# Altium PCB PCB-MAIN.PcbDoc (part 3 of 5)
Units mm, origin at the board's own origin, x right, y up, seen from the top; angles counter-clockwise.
Board outline 110 x 75 mm, 8 copper layers (F.Cu, In1.Cu, In2.Cu, In3.Cu, In4.Cu, In5.Cu, In6.Cu, B.Cu); 251 components, 185 nets, 1143 pads, 853 vias.
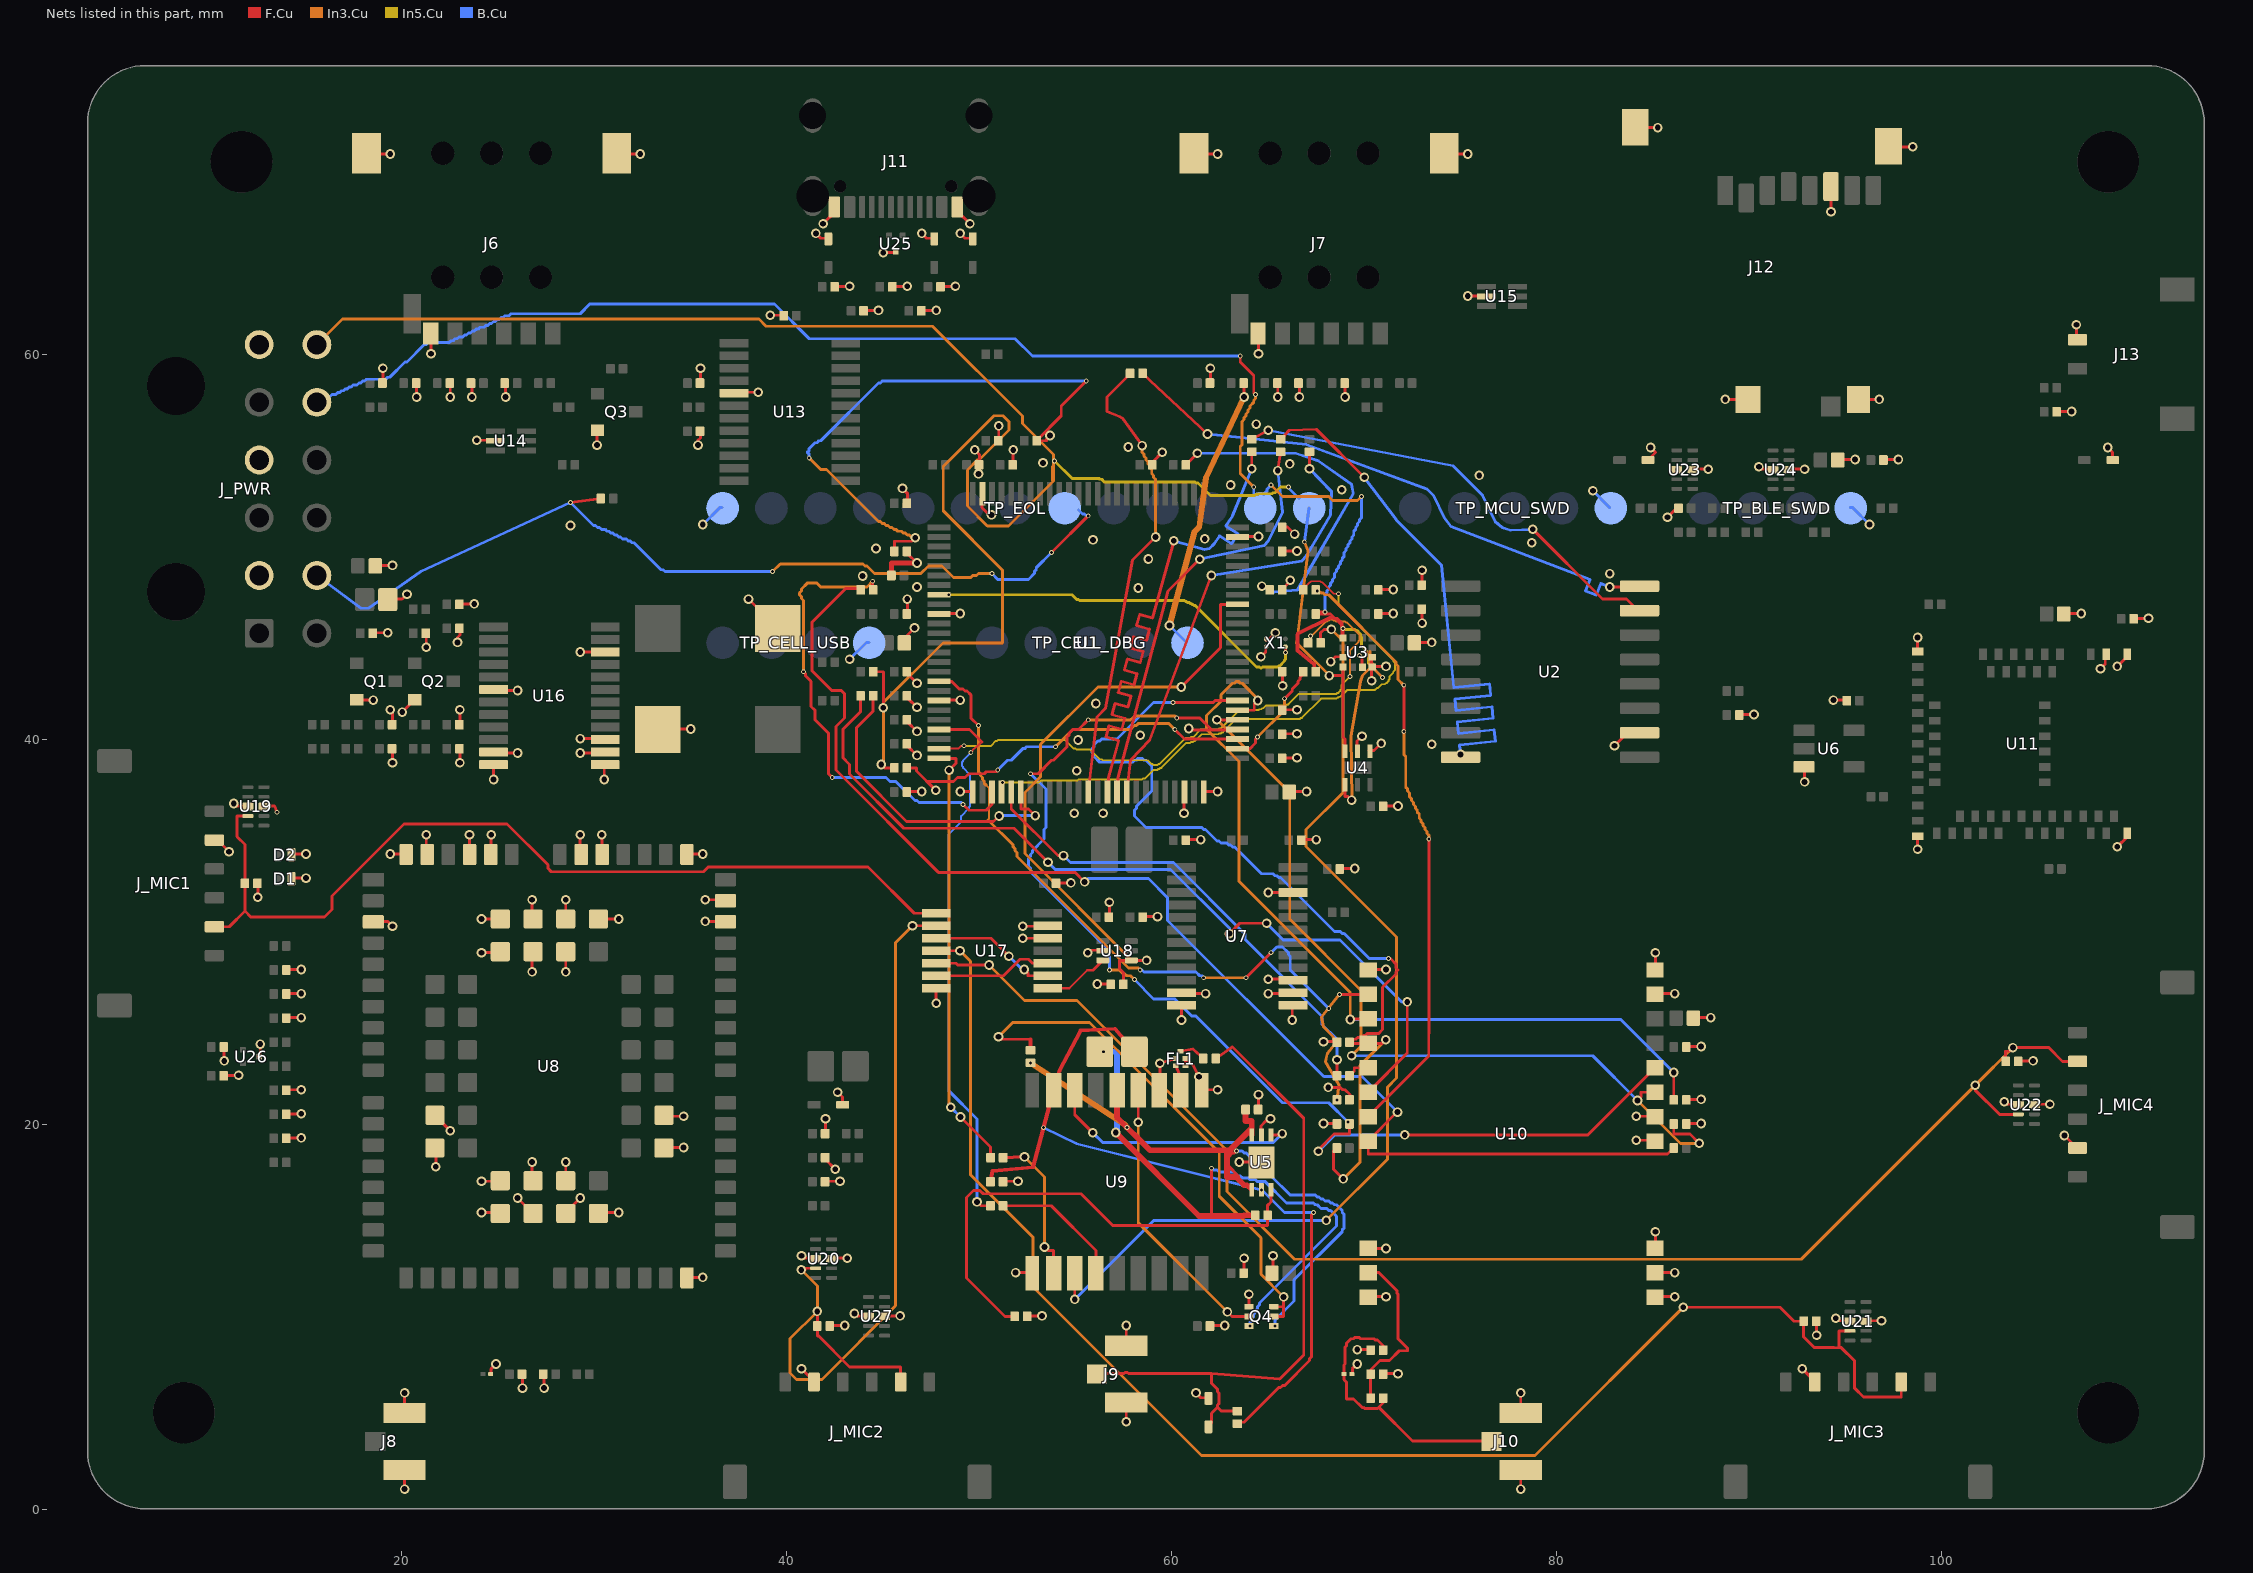
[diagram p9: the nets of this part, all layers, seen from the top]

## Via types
v1: diameter 0.5, hole 0.3, F.Cu to B.Cu, tented both sides, 579 vias
v2: diameter 0.25, hole 0.15, F.Cu to B.Cu, tented both sides, 274 vias

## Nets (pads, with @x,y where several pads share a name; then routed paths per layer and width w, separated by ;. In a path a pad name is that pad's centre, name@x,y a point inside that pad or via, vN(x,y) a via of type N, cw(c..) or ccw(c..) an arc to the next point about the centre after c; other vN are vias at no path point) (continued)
FAULT: J_PWR.8 R103.1 TP_EOL.8 | length 48.2
  F.Cu w0.15: v2(28.785,52.325) R103.1@30.36,52.525 ; v2(53.785,49.725) v2(55.685,51.625)
  In3.Cu w0.15: v2(39.285,48.725) 39.685,49.125 43.985,49.125 44.085,49.025 44.185,49.025 44.585,48.625 46.985,48.625 47.385,49.025 48.085,49.025 48.685,48.425 49.585,48.425 49.685,48.525 49.885,48.525 49.985,48.625 v2(50.685,48.625)
  B.Cu w0.15: J_PWR.8@15.605,48.525 17.885,46.825 18.285,46.825 20.985,48.725 v2(28.785,52.325) 29.985,51.125 30.085,51.125 30.185,51.025 30.285,51.025 30.385,50.925 30.585,50.925 30.685,50.825 30.785,50.825 30.885,50.725 30.985,50.725 31.085,50.625 31.185,50.625 31.285,50.525 31.385,50.525 31.485,50.425 31.685,50.425 31.785,50.325 31.885,50.325 31.985,50.225 32.085,50.225 33.485,48.825 33.585,48.825 33.685,48.725 v2(39.285,48.725) ; v2(50.685,48.625) 50.985,48.325 52.585,48.325 52.885,48.625 52.885,48.725 52.985,48.825 52.985,48.925 v2(53.785,49.725) ; TP_EOL.8@55.185,51.925 55.385,51.725 55.485,51.725 55.585,51.625 v2(55.685,51.625)
GND_DIGITAL: C1.2 C2.2 C3.2 C4.2 C5.2 C6.2 C7.2 C8.2 C9.2 C10.2 C11.2 C12.2 C13.2 C14.2 C15.2 C16.2 C17.2 C18.2 C19.2 C21.2 C22.2 C23.2 C24.2 C25.2 C26.2 C27.2 C28.2 C29.2 C31.2 C32.2 C60.2 C61.2 C62.2 C63.2 C65.2 C66.2 C67.2 C68.2 C69.2 C70.2 C71.2 C72.2 C73.2 C74.2 C75.2 C76.2 C77.2 C78.2 D4.2 D5.2 D6.2 D7.2 D8.2 D9.2 D11.2 FL1.B FL1.D FL1.E J9.SHIELD J10.SHIELD J11.A1 J11.A12 J11.B1 J11.B12 J12.6 J12.SHIELD J13.2 J_PWR.4 Q4.1 R2.2 R3.2 R5.2 R23.2 R60.2 R63.2 R64.2 R65.2 R66.2 R77.2 R93.2 R94.2 R96.2 R97.2 R98.2 TP_BLE_SWD.4 TP_EOL.1 TP_MCU_SWD.5 U1.10 U1.19 U1.26 U1.48 U1.50 U1.74 U1.99 U2.10 U3.3 U3.6 U3.7 U3.8 U4.4 U4.5 U5.5 U5.EP U6.3 U7.11 U7.12 U7.13 U7.14 U7.15 U7.22 U9.1 U9.10 U9.12 U10.1 U10.2 U10.3 U10.4 U10.5 U10.10 U10.11 U10.12 U10.20 U10.22 U11.1 U11.2 U11.15 U11.33 U11.55 U18.2 U23.3 U23.8 U24.3 U24.8 U25.3 X1.1 X1.4 | length 121.2
  F.Cu w0.15: C19.2@19.285,47.3 20.035,47.3 v1(20.285,47.55) ; v1(41.535,66.3) 41.785,66.05 D8.2@42.16,66.05 ; v1(41.91,66.8) 42.535,67.425 J11.B1@42.535,67.675 ; R94.2@42.535,63.55 v1(43.285,63.55) ; R98.2@44.035,62.3 v1(44.785,62.3) ; v1(45.035,65.3) U25.3@45.66,65.3 ; C77.2@45.535,63.55 v1(46.285,63.55) ; v1(46.035,53.05) 46.285,52.8 R96.2@46.285,52.3 ; C6.2@46.16,45.05 46.16,45.3 v1(46.66,45.8) ; C2.2@46.285,37.3 v1(47.035,37.3) ; C10.2@46.285,39.8 46.285,39.675 v1(46.785,39.175) ; C8.2@46.285,41.05 46.285,40.925 v1(46.785,40.425) ; C9.2@46.285,42.3 46.285,42.175 v1(46.785,41.675) ; C11.2@46.285,43.55 46.285,43.425 v1(46.785,42.925) ; C1.2@46.285,46.55 v1(46.285,47.3) ; R5.2@46.285,49.8 46.285,49.675 v1(46.785,49.175) ; R97.2@47.035,62.3 v1(47.785,62.3) ; v1(47.035,66.3) 47.285,66.05 D7.2@47.66,66.05 ; U1.19@47.91,42.05 v1(49.035,42.05) ; U1.10@47.91,46.55 v1(49.035,46.55) ; R93.2@48.035,63.55 v1(48.785,63.55) ; J11.B12@48.91,67.675 48.91,67.425 v1(49.535,66.8) ; v1(49.035,37.3) U1.26@49.66,37.3 ; v1(49.035,66.3) 49.285,66.05 D6.2@49.66,66.05 ; v1(49.785,55.05) 50.035,54.8 C5.2@50.035,54.3 ; U1.99@50.16,52.8 50.16,52.05 50.41,51.8 50.535,51.8 v1(50.66,51.675) ; C17.2@51.035,55.55 v1(51.035,56.3) ; C63.2@51.285,17.05 v1(52.035,17.05) ; C15.2@51.785,54.3 v1(51.785,55.05) ; v1(51.91,12.3) U9.1@52.785,12.3 ; R60.2@52.535,10.05 v1(53.285,10.05) ; v1(55.66,28.925) 55.785,29.05 U18.2@56.41,29.05 ; v1(56.16,27.3) R23.2@56.91,27.3 ; C31.2@56.785,30.8 v1(56.785,31.55) ; v1(57.66,4.55) J9.SHIELD@57.66,5.55 ; J9.SHIELD@57.66,8.55 v1(57.66,9.55) ; C32.2@58.535,30.8 v1(59.285,30.8) ; C18.2@59.035,54.3 59.035,54.425 v1(59.535,54.925) ; U9.12@59.41,21.8 v1(59.41,23.175) FL1.B@60.235,23.425 ; v1(60.535,25.425) U7.12@60.535,26.175 ; U7.11@60.535,26.8 v1(61.785,26.8) ; v1(60.66,36.175) U1.48@60.66,37.3 ; FL1.E@60.735,23.05 FL1.D@60.735,23.425 61.135,23.075 v1(61.435,22.475) ; C27.2@60.785,34.8 v1(61.535,34.8) ; v1(61.285,6.05) 61.535,5.8 D4.2@61.91,5.8 ; U9.10@61.535,21.8 v1(62.41,21.8) ; U1.50@61.66,37.3 v1(62.41,37.3) ; C62.2@62.035,9.55 v1(62.785,9.55) ; U1.74@63.41,50.55 v1(64.535,50.55) ; v1(63.535,18.05) U5.EP@64.66,18.05 ; C60.2@63.785,12.3 v1(63.785,13.05) ; Q4.1@64.035,10.55 v1(64.035,11.175) ; C65.2@64.535,20.8 v1(64.535,21.55) ; U5.5@64.66,19.425 64.66,19.925 64.91,20.175 65.035,20.175 v1(65.16,20.3) ; v1(64.66,44.3) 64.91,44.55 X1.1@64.91,44.8 ; X1.4@64.91,45.175 65.035,45.175 v1(65.41,45.55) ; v1(65.035,26.8) U7.14@66.285,26.8 ; v1(65.035,27.55) U7.15@66.285,27.55 ; v1(65.035,32.05) U7.22@66.285,32.05 ; C61.2@65.285,12.3 v1(65.285,13.175) ; C3.2@65.785,39.05 v1(66.535,39.05) ; C14.2@65.785,40.3 v1(66.535,40.3) ; C16.2@65.785,41.55 v1(66.535,41.55) ; v1(65.785,42.8) R2.2@65.785,43.55 ; R3.2@65.785,47.8 v1(66.185,48.275) ; C12.2@65.785,49.8 v1(66.535,49.8) ; C4.2@65.785,51.05 66.035,51.05 v1(66.41,50.675) ; C13.2@66.16,37.3 v1(67.035,37.3) ; v1(66.285,25.425) U7.13@66.285,26.175 ; C28.2@66.785,34.8 v1(67.535,34.8) ; v1(67.91,20.05) R63.2@68.66,20.05 ; v1(67.91,24.3) C68.2@68.66,24.3 ; v1(68.16,21.925) 68.785,21.925 68.91,21.8 69.035,21.8 69.285,21.55 R65.2@69.285,21.3 ; v1(68.285,44.05) 68.535,44.3 U3.3@68.91,44.3 ; C29.2@68.785,33.3 v1(69.535,33.3) ; D5.2@69.41,7.05 69.41,7.3 v1(69.66,7.55) ; v1(69.66,8.3) C70.2@70.41,8.3 ; U4.5@69.66,39.425 69.66,39.925 v1(69.91,40.175) ; v2(69.785,44.375) 69.91,44.3 U3.6@69.91,43.8 ; U10.22@70.285,11.05 v1(71.16,11.05) ; U10.20@70.285,13.55 v1(71.16,13.55) ; U10.12@70.285,28.05 v1(71.16,28.05) ; U4.4@70.285,39.425 70.535,39.425 v1(70.91,39.8) ; v1(70.41,43.05) U3.8@70.41,44.3 ; U3.7@70.41,43.8 v1(71.16,43.8) ; C23.2@70.785,46.55 v1(71.535,46.55) ; C25.2@70.785,47.8 v1(71.535,47.8) ; C69.2@71.035,7.05 v1(71.785,7.05) ; C26.2@71.035,36.55 v1(71.785,36.55) ; C24.2@72.66,45.05 v1(73.535,45.05) ; v1(73.035,46.05) C21.2@73.035,46.8 ; C22.2@73.035,48.05 v1(73.035,48.8) ; v1(78.16,1.05) J10.SHIELD@78.16,2.05 ; J10.SHIELD@78.16,5.05 v1(78.16,6.05) ; v1(83.035,39.675) 83.66,40.3 U2.10@84.285,40.3 ; v1(84.16,19.175) U10.4@85.16,19.175 ; v1(84.16,20.425) U10.5@85.16,20.425 ; J12.SHIELD@84.16,71.8 v1(85.285,71.8) ; D11.2@84.775,54.525 85.16,54.925 v1(84.91,55.175) ; U10.1@85.16,11.05 v1(86.16,11.05) ; U10.2@85.16,12.3 v1(86.16,12.3) ; U10.3@85.16,13.55 v1(85.16,14.425) ; U10.10@85.16,26.8 v1(86.16,26.8) ; U10.11@85.16,28.05 v1(85.16,28.925) ; v1(85.785,51.55) 86.285,52.05 C76.2@86.41,52.05 ; R64.2@86.785,20.05 v1(87.535,20.05) ; R66.2@86.785,21.3 v1(87.535,21.3) ; C66.2@86.785,24.05 v1(87.535,24.05) ; C67.2@87.16,25.55 v1(88.035,25.55) ; U23.8@87.16,54.05 v1(87.91,54.05) ; v1(88.785,57.675) J12.SHIELD@89.91,57.675 ; R77.2@89.535,41.3 v1(90.285,41.3) ; v1(90.535,54.175) 90.66,54.05 U24.3@91.285,54.05 ; U24.8@92.16,54.05 v1(92.91,54.05) ; v1(92.91,37.8) U6.3@92.91,38.55 ; v1(94.285,67.425) J12.6@94.285,68.675 ; v1(94.41,42.05) C73.2@95.16,42.05 ; C75.2@94.66,54.55 v1(95.535,54.55) ; J12.SHIELD@95.66,57.675 v1(96.785,57.675) ; C74.2@97.035,54.55 v1(97.785,54.55) ; J12.SHIELD@97.285,70.8 v1(98.535,70.8) ; v1(98.785,34.3) U11.33@98.785,34.925 ; U11.15@98.785,44.55 v1(98.785,45.3) ; C78.2@106.035,57.05 v1(106.785,57.05) ; C72.2@106.41,46.55 v1(107.285,46.55) ; J13.2@107.035,60.8 v1(107.035,61.55) ; v1(108.285,43.675) 108.535,43.925 U11.2@108.535,44.425 ; v1(108.66,55.175) 108.91,54.925 D9.2@108.91,54.55 ; v1(109.16,34.425) 109.66,34.925 U11.55@109.66,35.175 ; v1(109.16,43.8) 109.66,44.3 U11.1@109.66,44.425 ; C71.2@110.035,46.3 v1(110.785,46.3)
  F.Cu w0.25: C7.2@45.46,48.525 45.46,49.175 v1(46.785,49.175)
  B.Cu w0.15: v1(35.66,51.175) 36.535,52.05 TP_EOL.1@36.66,52.05 ; v1(81.91,52.925) TP_MCU_SWD.5@82.785,52.05 ; TP_BLE_SWD.4@95.285,52.05 95.41,52.05 v1(96.285,51.175)
  other v1: 54.96,36.175 56.46,36.175 55.085,38.375 73.535,39.75 55.16,39.975 58.385,40.225 56.085,41.875 58.285,47.875 46.785,47.925 43.96,48.5 82.785,48.625 58.814,49.384 44.66,49.925 78.735,50.225 55.935,50.375 61.735,50.425 28.785,51.125 68.86,52.975 63.085,53.225 76.001,53.725 49.985,53.805 66.16,54.325 53.335,54.375 57.76,55.2 64.411,56.392
  other v2: 86.267,54.025
GND_MIC: C20.2 C30.2 J_MIC1.2 J_MIC2.2 J_MIC3.2 J_MIC4.2 J_PWR.6 R19.2 R20.2 R21.2 R22.2 U17.7 U17.12 U17.13 U19.3 U19.8 U20.3 U20.8 U21.3 U21.8 U22.3 U22.8 | length 17.8
  F.Cu w0.15: J_MIC1.2@10.285,34.8 10.41,34.8 v1(11.035,34.175) ; v1(11.285,36.675) 11.41,36.55 U19.3@12.035,36.55 ; v1(12.535,31.8) R19.2@12.535,32.55 ; U19.8@12.91,36.55 13.41,36.55 v2(13.535,36.225) ; C20.2@18.66,49.05 v1(19.535,49.05) ; v1(40.785,7.3) J_MIC2.2@41.41,6.675 ; v1(40.785,13.175) 40.91,13.05 U20.3@41.535,13.05 ; R20.2@42.285,9.55 v1(43.035,9.55) ; U20.8@42.41,13.05 v1(43.16,13.05) ; v1(47.785,26.3) U17.7@47.785,27.05 ; v1(52.285,29.675) U17.12@53.535,29.675 ; v1(52.285,30.3) U17.13@53.535,30.3 ; C30.2@54.035,32.55 v1(54.785,32.55) ; v1(92.785,7.3) J_MIC3.2@93.41,6.675 ; v1(93.535,9.05) R21.2@93.535,9.8 ; v1(94.535,9.925) 94.66,9.8 U21.3@95.285,9.8 ; U21.8@96.16,9.8 v1(96.91,9.8) ; v1(103.285,21.175) 103.41,21.05 U22.3@104.035,21.05 ; R22.2@104.035,23.3 v1(104.785,23.3) ; U22.8@104.91,21.05 v1(105.66,21.05) ; v1(106.41,19.425) J_MIC4.2@107.035,18.8
GND_MODEM: C33.2 C34.2 C35.2 C36.2 C37.2 C38.2 C39.2 C40.2 C41.2 C42.2 C43.2 C44.2 C45.2 C46.2 C47.2 C48.2 C49.2 C50.2 C51.2 C52.2 C53.2 C54.2 C55.2 C56.2 C57.2 C58.2 C59.2 C79.2 C80.2 D1.2 D2.2 D3.2 D10.2 J6.4 J6.SHIELD J7.4 J7.SHIELD J8.SHIELD J_PWR.2 Q1.2 Q2.2 Q3.2 R25.2 R27.2 R29.2 R34.2 R35.2 R45.2 R47.2 TP_CELL_DBG.5 TP_CELL_USB.4 U8.3 U8.31 U8.47 U8.48 U8.50 U8.54 U8.55 U8.58 U8.59 U8.61 U8.62 U8.67 U8.68 U8.69 U8.70 U8.71 U8.72 U8.73 U8.74 U8.79 U8.80 U8.81 U8.82 U8.89 U8.90 U8.91 U8.100 U8.101 U8.102 U13.5 U14.2 U15.2 U16.6 U16.11 U16.12 U16.13 U16.14 U16.15 U16.22 U26.3 U27.3 U27.8 | length 101.3
  F.Cu w0.15: C37.2@10.785,22.55 v1(11.535,22.55) ; v1(10.785,23.3) C38.2@10.785,24.05 ; U26.3@12.66,23.55 v1(12.66,24.175) ; C45.2@14.035,19.3 v1(14.785,19.3) ; C41.2@14.035,20.55 v1(14.785,20.55) ; C39.2@14.035,21.8 v1(14.785,21.8) ; C40.2@14.035,25.55 v1(14.785,25.55) ; C43.2@14.035,26.8 v1(14.785,26.8) ; C47.2@14.035,28.05 v1(14.785,28.05) ; D1.2@14.285,32.8 v1(15.035,32.8) ; D2.2@14.285,34.05 v1(15.035,34.05) ; Q1.2@17.66,42.05 v1(18.535,42.05) ; J6.SHIELD@18.16,70.425 v1(19.41,70.425) ; U8.3@18.535,30.55 19.285,30.55 v1(19.535,30.3) ; R25.2@18.535,45.55 v1(19.285,45.55) ; C50.2@19.035,58.55 v1(19.035,59.3) ; v1(19.41,34.05) U8.62@20.285,34.05 ; v1(19.41,41.55) 19.535,41.425 R27.2@19.535,40.8 ; v1(19.535,38.8) R34.2@19.535,39.55 ; v1(20.035,41.425) Q2.2@20.66,42.05 ; v1(20.16,1.05) J8.SHIELD@20.16,2.05 ; J8.SHIELD@20.16,5.05 v1(20.16,6.05) ; v1(20.785,57.8) C52.2@20.785,58.55 ; U8.61@21.285,34.05 v1(21.285,35.05) ; v1(21.285,44.8) R29.2@21.285,45.55 ; v1(21.535,60.05) J6.4@21.535,61.05 ; v1(21.785,17.8) U8.68@21.785,18.8 ; U8.67@21.785,20.425 v1(22.535,19.675) ; v1(22.535,57.8) C54.2@22.535,58.55 ; v1(22.91,45.05) 22.91,45.3 23.035,45.425 C33.2@23.035,45.8 ; v1(23.035,38.8) C48.2@23.035,39.55 ; C35.2@23.035,40.8 v1(23.035,41.55) ; C34.2@23.035,47.05 v1(23.785,47.05) ; U8.59@23.535,34.05 v1(23.535,35.05) ; v1(23.66,57.8) C55.2@23.66,58.55 ; v1(23.91,55.55) U14.2@24.91,55.55 ; v1(24.16,15.425) U8.69@25.16,15.425 ; v1(24.16,17.05) U8.89@25.16,17.05 ; v1(24.16,28.925) U8.102@25.16,28.925 ; v1(24.16,30.675) U8.82@25.16,30.675 ; D3.2@24.66,7.05 24.66,7.3 v1(24.91,7.55) ; U8.58@24.66,34.05 v1(24.66,35.05) ; v1(24.785,37.925) U16.12@24.785,38.675 ; U16.11@24.785,39.3 v1(26.035,39.3) ; U16.6@24.785,42.55 v1(26.035,42.55) ; v1(25.41,57.8) C56.2@25.41,58.55 ; v1(26.035,16.175) U8.70@26.785,15.425 ; v1(26.285,6.3) C80.2@26.285,7.05 ; U8.90@26.785,17.05 v1(26.785,18.05) ; v1(26.785,27.925) U8.101@26.785,28.925 ; U8.81@26.785,30.675 v1(26.785,31.675) ; v1(27.41,6.3) C79.2@27.41,7.05 ; U8.71@28.535,15.425 v1(29.285,16.175) ; U8.91@28.535,17.05 v1(28.535,18.05) ; v1(28.535,27.925) U8.100@28.535,28.925 ; U8.80@28.535,30.675 v1(28.535,31.675) ; U8.55@29.285,34.05 v1(29.285,35.05) ; v1(29.285,39.3) U16.14@30.535,39.3 ; v1(29.285,40.05) U16.15@30.535,40.05 ; v1(29.285,44.55) U16.22@30.535,44.55 ; v1(30.16,55.3) Q3.2@30.16,56.05 ; U8.72@30.285,15.425 v1(31.285,15.425) ; U8.79@30.285,30.675 v1(31.285,30.675) ; U8.54@30.41,34.05 v1(30.41,35.05) ; v1(30.535,37.925) U16.13@30.535,38.675 ; J6.SHIELD@31.16,70.425 v1(32.41,70.425) ; C36.2@33.285,40.55 v1(35.035,40.55) ; U8.73@33.66,18.8 v1(34.66,18.8) ; U8.74@33.66,20.425 v1(34.66,20.425) ; U8.31@34.785,12.05 v1(35.66,12.05) ; U8.50@34.785,34.05 v1(35.66,34.05) ; v1(35.41,55.3) 35.41,55.55 35.535,55.675 C49.2@35.535,56.05 ; R47.2@35.535,58.55 v1(35.535,59.3) ; v1(35.785,30.55) U8.47@36.785,30.55 ; v1(35.785,31.675) U8.48@36.785,31.675 ; U13.5@37.285,58.05 v1(38.535,58.05) ; v1(38.035,47.3) C44.2@39.535,45.8 ; v1(39.16,62.05) R45.2@39.91,62.05 ; R35.2@42.035,17.05 v1(42.785,17.05) ; C46.2@42.035,18.3 42.035,18.175 v1(42.535,17.675) ; C42.2@42.035,19.55 v1(42.035,20.3) ; v1(42.66,21.675) 42.91,21.425 D10.2@42.91,21.05 ; v1(43.535,10.175) 43.66,10.05 U27.3@44.285,10.05 ; U27.8@45.16,10.05 v1(45.91,10.05) ; J7.SHIELD@61.16,70.425 v1(62.41,70.425) ; C51.2@62.035,58.55 v1(62.035,59.3) ; v1(63.785,57.8) C53.2@63.785,58.55 ; v1(64.535,60.05) J7.4@64.535,61.05 ; v1(65.535,57.8) C57.2@65.535,58.55 ; v1(66.66,57.8) C58.2@66.66,58.55 ; v1(69.035,57.8) C59.2@69.035,58.55 ; J7.SHIELD@74.16,70.425 v1(75.41,70.425) ; v1(75.41,63.05) U15.2@76.41,63.05
  In3.Cu w0.3: v1(59.91,45.925) 61.21,50.8 61.46,51.05 61.81,53.6 v1(63.785,57.8)
  B.Cu w0.15: v1(43.285,44.175) 44.16,45.05 TP_CELL_USB.4@44.285,45.05 ; v1(59.91,45.925) TP_CELL_DBG.5@60.785,45.05
GNSS_ANT_BIAS_RAW: C65.1 Q4.4 R61.1 U5.3 U5.4 U9.14 | length 36.6
  F.Cu w0.15: v2(63.385,18.625) 63.285,18.525 63.185,18.525 62.985,18.325 62.985,17.825 63.485,17.325 63.485,17.225 63.585,17.125 63.585,17.025
  F.Cu w0.25: 63.784,16.85 63.935,16.85 U5.3@64.185,16.6
  F.Cu w0.3: U9.14@57.185,21.775 57.185,20.523 57.185,20.359 58.89,18.654 62.892,18.654 ; 63.784,16.85 63.359,17.275 62.892,17.275 62.892,18.654 ; C65.1@63.86,20.775 63.86,20.173 64.164,20.173 64.185,20.152 64.185,19.801 ; U5.4@64.185,19.45 64.185,19.801 ; 62.892,18.654 63.038,18.654 64.185,19.801
  In3.Cu w0.3: v2(52.685,23.2) 57.585,20 v2(57.702,19.842)
  B.Cu w0.15: v2(63.385,18.625) 63.685,18.625 63.785,18.525 63.885,18.525 65.085,17.325 65.185,17.325 66.185,16.325 67.485,16.325 67.585,16.225 67.685,16.225 67.785,16.125 67.885,16.125 67.985,16.025 68.185,16.025 68.285,15.925 68.385,15.925 68.485,15.825 68.585,15.825 68.885,15.525 68.885,15.425 68.985,15.325 68.985,14.625 68.885,14.525 68.885,14.425 66.385,11.925 66.385,10.825 65.385,9.825 v2(65.385,9.525)
GNSS_ANT_DETECT: U5.6 U9.16 | length 13.5
  F.Cu w0.15: U9.16@54.985,21.775 54.985,20.504 v1(55.924,19.565) ; U5.6@65.185,19.45 65.695,19.45 v1(65.769,19.524)
  B.Cu w0.15: v1(55.924,19.565) 56.435,19.053 65.298,19.053 v1(65.769,19.524)
GNSS_ANT_DIV: R59.2 R60.1 U5.1 | length 26
  F.Cu w0.15: R60.1@51.86,10.025 51.358,10.025 49.364,12.019 49.364,16.206 49.73,16.572 50.053,16.572 50.226,16.4 55.308,16.4 56.96,14.748 65.01,14.748 R59.2@65.01,15.275 65.01,15.802 65.181,15.973 65.185,15.973 U5.1@65.185,16.6
GNSS_ANT_GATE: Q4.5 Q4.6 R61.2 | length 28.3
  F.Cu w0.15: v1(51.025,24.556) 51.156,24.425 51.207,24.425 52.685,24.425 ; Q4.5@65.323,10.025 65.839,10.025 65.839,10.525 ; v1(65.839,11.039) 65.839,10.525 ; 65.839,10.525 Q4.6@65.323,10.525 65.839,10.525
  F.Cu w0.2: R61.2@52.685,23.85 52.685,24.425
  In3.Cu w0.15: v1(51.025,24.556) 51.761,25.292 55.75,25.292 62.497,18.546 62.497,16.271 64.659,14.108 64.659,12.219 v1(65.839,11.039)
GNSS_ANT_OFF_N: Q4.2 U9.13 | length 14.7
  F.Cu w0.15: v1(58.285,20.113) U9.13@58.285,21.775 ; v1(62.919,10.259) 63.153,10.025 Q4.2@64.047,10.025
  In3.Cu w0.15: v1(58.285,20.113) 58.285,14.893 v1(62.919,10.259)
GNSS_ANT_SHORT_N: C63.1 L2.1 R62.2 U5.2 U9.17 | length 41.3
  F.Cu w0.15: L2.1@63.585,4.525 63.785,4.525 65.585,6.325 65.685,6.325 65.785,6.425 65.885,6.425 67.185,7.725 67.185,7.825 67.285,7.925 67.285,15.325 v2(67.385,15.425)
  F.Cu w0.2: C63.1@50.61,17.025 50.71,17.575 52.81,17.775 U9.17@53.885,21.775 54.185,22.775 55.285,24.875 57.085,24.975 R62.2@58.085,23.775
  B.Cu w0.15: v2(53.363,19.831) 55.085,19 v2(64.685,16.6) ; v2@64.685,16.625 65.885,15.425 v2(67.385,15.425)
GNSS_ANT_SWITCHED: Q4.3 R59.1 R62.1 | length 31.6
  F.Cu w0.15: 62.085,15.225 v2(62.085,17.725)
  F.Cu w0.3: v1(57.113,19.58) 61.447,15.246 63.754,15.246 63.783,15.275 R59.1@64.36,15.275
  B.Cu w0.15: v2(62.085,17.725) 62.185,17.625 62.385,17.625 62.485,17.525 63.285,17.525 63.485,17.325 63.585,17.325 63.685,17.225 63.985,17.225 64.085,17.125 64.385,17.125 64.485,17.025 64.885,17.025 65.985,15.925 67.385,15.925 67.485,15.825 67.585,15.825 67.785,15.625 68.085,15.625 68.185,15.525 68.285,15.525 68.585,15.225 68.585,14.725 64.585,10.725 64.585,10.625 64.485,10.525 64.485,10.425 64.385,10.325 64.385,10.225 64.285,10.125 64.285,10.025 64.185,9.925 64.185,9.825 64.085,9.725 v2(64.085,9.525)
  B.Cu w0.3: v2(56.485,23.775) 57.185,23.775 57.185,19.652 v1(57.113,19.58)
GNSS_PPS_U1: R58.2 U1.22 | length 28.8
  F.Cu w0.1: v2(49.585,39.325) 49.685,39.425 49.685,39.475 50.17,39.875
  F.Cu w0.15: U1.22@47.935,40.525 49.52,40.525 50.17,39.875 ; v1(49.907,15.974) 49.909,15.974 50.108,15.775 R58.2@50.61,15.775
  B.Cu w0.1: 48.485,35.125 49.085,35.725 49.085,36.025 49.485,36.425 49.485,36.475 49.535,36.525 49.535,38.175 49.185,38.525 49.185,38.575 49.135,38.625 49.135,38.825 49.185,38.875 49.185,38.925 v2(49.585,39.325)
  B.Cu w0.15: 48.438,35.078 48.438,21.751 49.907,20.282 v1(49.907,15.974)
GNSS_PPS_U9: R58.1 U9.4 | length 7
  F.Cu w0.15: R58.1@51.26,15.775 51.762,15.775 53.762,15.775 56.085,13.452 U9.4@56.085,12.275
GNSS_RF_ANT_BIASED: C64.1 D4.1 J9.1 L2.2 | length 34.1
  F.Cu w0.151: J9.1@56.16,7.05 57.535,7.05 57.597,7.113 57.722,7.113 57.785,7.05 62.097,7.05 ; D4.1@61.91,4.3 62.097,4.488 62.097,4.988 62.41,5.3 ; C64.1@62.31,23.425 63.185,24.025 66.885,20.325 66.885,8.025 65.635,6.775 62.097,7.05 ; L2.2@63.41,5.113 62.597,5.113 62.41,5.3 ; 62.097,7.05 62.097,6.55 62.41,6.238 62.41,6.112 62.472,6.05 62.472,5.487 62.41,5.425 62.41,5.3
GNSS_RF_DC_BLOCK: C64.2 FL1.C | length 1.4
  F.Cu w0.151: FL1.C@60.485,23.8 61.135,23.925 C64.2@61.66,23.425
GNSS_RF_FILTERED: FL1.A U9.11 | length 1.3
  F.Cu w0.151: FL1.A@60.235,23.05 60.485,22.475 U9.11@60.485,21.775
GNSS_RX_U1: R56.2 U1.25 | length 22.7
  F.Cu w0.15: U1.25@47.935,39.025 48.812,39.025 48.812,38.768 v1@48.458,38.414 ; v1(49.046,20.389) 50.61,18.825 R56.2@50.61,18.275
  In3.Cu w0.15: v1(48.456,38.414) 48.456,20.978 v1(48.542,20.893)
  B.Cu w0.15: v1(48.542,20.893) v1(49.046,20.389)
GNSS_RX_U9: R56.1 U9.2 | length 8
  F.Cu w0.15: R56.1@51.26,18.275 51.762,18.275 51.798,18.311 v1(52.374,18.311) ; v1(53.413,13.629) 53.59,13.452 53.885,13.452 U9.2@53.885,12.275
  In3.Cu w0.15: v1(52.374,18.311) 53.413,17.272 v1(53.413,13.629)
GNSS_TX_U1: R57.1 U1.24 | length 29.6
  F.Cu w0.1: U1.24@48.385,39.525 48.935,39.525 49.085,39.675 v2(49.235,39.675) ; R57.1@67.135,45.125 67.185,45.175 67.185,45.225 67.235,45.275 v2(67.235,45.375)
  In3.Cu w0.1: v2(67.235,45.375) 67.285,45.375 68.035,46.125 68.085,46.125 68.135,46.175 68.185,46.175 68.235,46.225 68.385,46.225 68.435,46.175 68.535,46.175 68.585,46.125 69.035,46.125 69.085,46.075 69.135,46.075 69.785,45.425 69.785,45.175 69.735,45.125 69.735,45.075 69.285,44.625 v2(69.285,43.275)
  In5.Cu w0.1: v2(49.235,39.675) 50.635,39.675 50.885,39.925 50.935,39.925 50.985,39.975 54.485,39.975 54.935,39.525 55.035,39.525 55.085,39.475 55.785,39.475 56.285,38.975 56.385,38.975 56.435,38.925 58.785,38.925 58.985,38.725 59.035,38.725 59.085,38.675 59.285,38.675 59.335,38.725 59.385,38.725 60.735,40.075 60.985,40.075 61.035,40.125 61.135,40.125 61.535,40.525 62.435,40.525 62.485,40.575 62.585,40.575 63.535,41.525 64.535,41.525 64.585,41.575 64.685,41.575 64.735,41.625 64.785,41.625 64.935,41.775 65.985,41.775 66.035,41.825 66.085,41.825 66.635,42.375 68.585,42.375 68.635,42.425 68.685,42.425 68.785,42.525 68.785,42.575 68.835,42.625 68.835,42.825 v2(69.285,43.275)
GNSS_TX_U9: R57.2 U9.3 | length 52.5
  F.Cu w0.15: v1(54.985,10.908) U9.3@54.985,12.275 ; R57.2@67.76,45.025 67.76,45.552 67.932,45.724 v1(68.323,45.724)
  In3.Cu w0.15: v1(68.049,15.013) 71.229,18.193 71.229,21.935 71.703,22.408 71.703,29.745 67.005,34.443 67.005,35.327 68.918,37.24 68.918,45.129 v1(68.323,45.724)
  B.Cu w0.15: v1(54.985,10.908) 59.09,15.013 v1(68.049,15.013)
HW_REV0: R3.1 R4.2 | length 18
  F.Cu w0.15: R4.2@60.76,54.275 v1(61.36,54.875) ; v1(64.71,47.975) R3.1@65.11,47.775
  B.Cu w0.15: v1(61.36,54.875) 66.46,54.875 67.66,54.475 69.36,53.275 69.46,52.775 66.56,47.775 65.36,47.675 v1(64.71,47.975)
HW_REV1: R5.1 R6.2 | length 30.1
  F.Cu w0.15: R5.1@45.61,49.775 45.61,50.302 46.509,50.302 v1(46.698,50.491) ; R6.2@53.01,55.525 53.512,55.525 53.512,55.612 v1(53.701,55.801) ; R6.2@53.085,55.625 54.285,56.825 54.285,57.325 v2(55.585,58.625)
  In3.Cu w0.15: v2(41.185,54.625) 41.785,54.025 42.085,54.025 44.785,51.325 44.885,51.325 44.985,51.225 45.085,51.225 45.185,51.125 45.285,51.125 45.385,51.025 45.485,51.025 45.585,50.925 45.685,50.925 45.785,50.825 45.985,50.825 46.085,50.725 46.185,50.725 46.285,50.625 46.385,50.625 46.485,50.525 v1@46.585,50.525
  B.Cu w0.15: v2(41.185,54.625) 41.185,54.825 41.085,54.925 41.185,55.025 41.185,55.125 41.485,55.425 41.585,55.425 41.685,55.525 41.785,55.525 44.785,58.525 44.885,58.525 44.985,58.625 v2(55.585,58.625)
I2C2_SCL_BUS: J_PWR.11 R13.2 R15.2 TP_EOL.12 U3.1 U4.1 | length 93.9
  F.Cu w0.15: v2(63.585,59.925) 63.585,59.625 64.285,58.925 64.285,58.025 v2(64.385,57.925) ; R13.2@67.51,46.525 68.012,46.525 68.267,46.525 68.922,45.87 U3.1@68.922,45.275 ; R13.2@67.585,46.525 67.685,46.625 v2(67.985,46.625) ; U4.1@69.035,37.66 69.035,37.033 69.192,37.033 v1(69.37,36.855)
  F.Cu w0.2: R15.2@67.51,43.525 67.41,43.925 66.56,44.625 66.56,45.425 66.61,45.525 68.26,46.325 68.61,46.275 68.86,46.025 U3.1@68.922,45.275
  In3.Cu w0.15: v2(64.285,53.125) 63.585,53.825 63.585,55.225 63.685,55.325 63.685,56.525 63.785,56.625 63.785,56.725 63.885,56.825 63.885,56.925 63.985,57.025 63.985,57.125 64.085,57.225 64.085,57.325 64.285,57.525 64.285,57.625 64.385,57.725 v2(64.385,57.925) ; v2(65.185,53.225) 65.785,52.625 68.185,52.625 68.385,52.425 69.685,52.425 v2(69.885,52.625) ; v2(68.922,45.77) v2@68.935,45.775 ; v1(69.37,36.855) 69.385,36.875 69.335,40.175 69.835,43.025 69.935,43.325 70.335,43.725 70.335,44.575 70.335,44.075 70.485,43.925 70.485,43.725 v2(70.985,43.225)
  In5.Cu w0.15: v2@69.035,45.725 69.535,45.725 69.585,45.675 69.635,45.675 69.835,45.475 69.835,45.375 69.885,45.325 69.885,44.875 70.185,44.575 70.185,44.475 70.235,44.425 70.235,43.975 v2(70.985,43.225)
  B.Cu w0.15: J_PWR.11@16.185,57.825 16.285,57.825 16.385,57.925 16.585,57.925 16.685,58.025 16.785,58.025 16.885,58.125 16.985,58.125 17.085,58.225 17.185,58.225 17.285,58.325 17.385,58.325 17.485,58.425 17.685,58.425 17.785,58.525 17.885,58.525 17.985,58.625 18.085,58.625 18.185,58.725 19.185,58.725 19.285,58.825 19.385,58.825 20.185,59.625 20.285,59.625 21.185,60.525 21.285,60.525 21.385,60.625 22.485,60.625 22.585,60.725 22.685,60.725 22.785,60.825 22.885,60.825 22.985,60.925 23.185,60.925 23.285,61.025 23.385,61.025 23.485,61.125 23.585,61.125 23.685,61.225 23.785,61.225 23.885,61.325 23.985,61.325 24.085,61.425 24.285,61.425 24.385,61.525 24.485,61.525 24.585,61.625 24.685,61.625 24.785,61.725 24.885,61.725 24.985,61.825 25.085,61.825 25.185,61.925 25.285,61.925 25.385,62.025 25.585,62.025 25.685,62.125 29.285,62.125 29.785,62.625 39.385,62.625 41.185,60.825 51.885,60.825 52.785,59.925 v2(63.585,59.925) ; TP_EOL.12@64.285,52.725 v2(64.285,53.125) ; TP_EOL.12@64.785,52.725 64.985,52.925 64.985,53.025 v2(65.185,53.225) ; v2(67.985,46.625) 67.985,47.525 68.085,47.625 68.085,47.725 68.185,47.825 68.185,47.925 68.285,48.025 68.285,48.125 68.385,48.225 68.385,48.325 68.485,48.425 68.485,48.625 68.585,48.725 68.585,48.825 68.685,48.925 68.685,49.025 68.785,49.125 68.785,49.225 68.885,49.325 68.885,49.425 68.985,49.525 68.985,49.725 69.085,49.825 69.085,49.925 69.185,50.025 69.185,50.125 69.285,50.225 69.285,50.325 69.385,50.425 69.385,50.525 69.485,50.625 69.485,50.825 69.585,50.925 69.585,51.025 69.685,51.125 69.685,51.225 69.785,51.325 69.785,51.425 69.885,51.525 v2(69.885,52.625)
I2C2_SCL_U1: R15.1 U1.52 | length 5.2
  F.Cu w0.15: U1.52@63.885,39.525 64.085,39.525 64.385,39.825 64.385,40.025 v2(64.485,40.125) ; v2(65.885,42.125) 66.285,42.525 66.285,42.625 66.585,42.925 66.585,43.025 66.685,43.125 66.685,43.225 66.785,43.325 R15.1@66.785,43.425
  In3.Cu w0.15: v2(64.485,40.125) 65.885,41.525 v2(65.885,42.125)
I2C2_SDA_BUS: J_PWR.12 R14.2 R16.2 TP_EOL.13 U3.4 U4.6 | length 113.1
  F.Cu w0.15: R14.2@44.51,43.525 45.012,43.525 45.037,43.5 v1(45.037,41.658) ; v1(44.928,38.705) 45.108,38.525 R16.2@45.61,38.525 ; v1(68.215,43.323) 68.922,43.323 ; U3.4@68.922,43.775 68.922,43.323 ; U4.6@69.035,39.39 69.035,40.017 68.922,40.129 68.922,43.323
  In3.Cu w0.15: J_PWR.12@15.605,60.525 16.929,61.849 38.575,61.849 38.946,61.478 47.597,61.478 52.265,56.81 52.265,56.429 53.876,54.818 53.876,53.433 51.54,51.097 50.443,51.097 49.406,52.134 49.406,54.008 49.921,54.523 50.003,54.523 51.562,56.082 51.562,56.518 51.253,56.827 50.788,56.827 48.153,54.192 48.153,51.885 51.238,48.801 51.238,45.021 48.136,45.021 45.037,41.922 v1(45.037,41.658) 45.037,38.814 v1(44.928,38.705) ; 53.835,53.475 53.835,54.175 53.885,54.225 53.885,54.425 v2(53.935,54.475) ; v2(66.915,50.275) 67.115,49.775 66.518,45.021 v1(68.215,43.323)
  In5.Cu w0.15: v2(53.935,54.475) 54.835,53.575 56.235,53.575 56.285,53.525 56.385,53.525 56.535,53.375 61.235,53.375 61.285,53.325 61.385,53.325 62.035,52.675 64.335,52.675 64.385,52.725 64.485,52.725 64.535,52.775 65.235,52.775 65.285,52.825 65.385,52.825 65.685,53.125 v2(66.085,53.125)
  B.Cu w0.15: v2(66.085,53.125) 66.085,53.075 TP_EOL.13@66.635,52.525 ; v2(66.915,50.275) TP_EOL.13@67.165,52.025
I2C2_SDA_U1: R16.1 U1.53 | length 19.4
  F.Cu w0.15: R16.1@46.26,38.525 46.762,38.525 46.762,38.361 v1(47.762,37.361) ; 47.285,37.825 48.685,37.825 48.885,38.025 49.285,38.025 49.485,38.225 50.285,38.225 50.385,38.325 50.885,38.325 v2(50.985,38.425) ; v2(60.185,40.525) 60.685,40.025 U1.53@62.985,40.025
  In3.Cu w0.15: v2(53.985,39.625) 54.885,40.525 57.885,40.525 58.085,40.725 58.185,40.725 58.285,40.825 59.885,40.825 v2(60.185,40.525)
  B.Cu w0.15: v2(50.985,38.425) 51.485,38.925 51.685,38.925 52.285,39.525 52.385,39.525 52.485,39.625 v2(53.985,39.625)
LORA_BUSY: R66.1 U1.56 U10.14 | length 44.6
  F.Cu w0.15: U1.56@63.435,41.525 64.312,41.525 64.312,41.844 v1(64.494,42.027) ; v1(69.304,25.453) 69.335,25.485 U10.14@70.235,25.485 ; R66.1@86.11,21.275 v1(86.11,22.699)
  In3.Cu w0.15: 62.585,42.025 62.585,42.325 63.185,42.925 63.285,42.925 63.385,43.025 63.485,43.025 63.585,42.925 63.685,42.925 v1@64.485,42.125 ; 62.62,42.027 61.838,41.245 61.838,40.534 63.514,38.859 63.514,32.639 69.304,26.849 v1(69.304,25.453)
  B.Cu w0.15: v1(69.304,25.453) 83.356,25.453 v1(86.11,22.699)
LORA_DIO1: R65.1 U1.17 U10.13 | length 39.9
  F.Cu w0.15: U1.17@48.385,43.025 48.585,43.025 48.985,42.625 49.185,42.625 49.285,42.525 49.385,42.525 49.585,42.325 49.585,41.125 v2(49.985,40.725) ; v2(63.885,27.625) v2(65.185,28.925) ; v2(68.735,26.755) U10.13@70.235,26.755
  In3.Cu w0.1: 50.435,37.575 50.535,37.475 50.535,35.875
  In3.Cu w0.15: v2(49.985,40.725) 49.985,38.325 50.085,38.225 50.085,38.125 50.185,38.025 50.185,37.925 50.285,37.825 50.285,37.725 50.385,37.625 ; 50.485,35.825 51.785,34.525 51.785,34.425 51.885,34.325 51.885,34.225 51.985,34.125 51.985,33.925 57.785,28.125 58.285,28.125 v2(58.385,28.025) ; v2(61.685,27.625) v2(63.885,27.625) ; v2(68.61,21.275) 68.71,22.075 68.01,23.275 68.11,23.675 68.51,24.175 68.41,24.575 67.91,25.075 67.81,25.575 v2(68.735,26.755)
  B.Cu w0.15: v2(58.385,28.025) 58.485,28.025 58.585,27.925 61.285,27.925 61.485,27.725 61.585,27.725 v2(61.685,27.625) ; v2(65.185,28.925) 65.485,29.225 65.785,29.225 66.085,28.925 66.085,28.825 66.185,28.725 66.185,28.025 v2(68.185,26.025)
LORA_MISO_U1: R72.2 U1.30 | length 25.1
  F.Cu w0.15: U1.30@51.685,37.275 51.685,36.398 54.114,33.97 v1(54.4,33.97) ; R72.2@68.61,22.525 v1(68.61,23.362)
  B.Cu w0.15: v1(54.4,33.97) 54.767,33.603 60.111,33.603 63.822,29.891 63.822,29.632 67.841,25.614 67.841,25.198 68.61,24.429 v1(68.61,23.362)
LORA_MISO_U10: R72.1 U10.16 | length 1.2
  F.Cu w0.15: R72.1@69.26,22.525 69.508,22.773 69.508,22.945 U10.16@70.235,22.945
LORA_MOSI_U1: R71.1 U1.31 | length 16.6
  F.Cu w0.15: R71.1@44.51,42.275 44.51,41.481 43.64,40.611 43.64,38.353 46.249,35.743 50.771,35.743 v1(51.056,36.028) ; U1.31@52.185,37.275 52.185,36.398 52.586,36.398 v1(52.937,36.048)
  B.Cu w0.15: v1(51.056,36.028) 51.075,36.048 v1(52.937,36.048)
LORA_MOSI_U10: R71.2 U10.17 | length 44.6
  F.Cu w0.15: R71.2@43.86,42.275 43.86,41.456 42.936,40.533 42.936,39.056 43.288,38.705 43.288,38.207 46.104,35.392 51.829,35.392 v1(53.593,33.628) ; v1(63.022,29.916) 63.561,30.455 v1(64.954,30.455) ; U10.17@70.235,21.675 72.265,23.705 v1(72.265,26.368)
  B.Cu w0.15: v1(53.593,33.628) 53.969,33.251 59.965,33.251 63.022,30.194 v1(63.022,29.916) ; v1(64.954,30.455) 65.823,29.586 68.763,29.586 71.981,26.368 v1(72.265,26.368)
LORA_NSS_U1: R69.1 U1.28 | length 24.3
  F.Cu w0.15: v2(40.885,43.525) 40.985,43.425 40.985,43.325 41.285,43.025 41.285,41.725 41.485,41.525 41.485,41.025 42.185,40.325 42.185,38.225 v2(42.385,38.025) ; R69.1@44.485,47.825 v2(44.485,48.225) ; v2(49.185,36.625) 49.485,36.325 50.385,36.325 50.685,36.625 U1.28@50.685,36.825
  In3.Cu w0.15: v2(40.885,43.525) 40.885,47.225 40.785,47.325 40.785,47.425 40.685,47.525 40.685,47.625 40.785,47.725 40.785,47.825 41.085,48.125 41.585,48.125 41.785,47.925 44.185,47.925 v2(44.485,48.225)
  B.Cu w0.15: v2(42.385,38.025) 45.185,38.025 45.385,37.825 45.685,37.825 46.685,36.825 46.785,36.825 46.885,36.725 49.085,36.725 v2(49.185,36.625)
LORA_NSS_U10: R68.2 R69.2 U10.19 | length 68.3
  F.Cu w0.15: R69.2@43.86,47.775 43.789,47.846 43.082,47.846 41.334,46.098 41.334,43.575 42.357,42.552 42.85,42.552 43.024,42.378 43.024,41.118 42.585,40.678 42.585,38.413 47.897,33.101 54.998,33.101 v1(55.498,32.601) ; v1(71.756,20.639) 71.739,20.639 U10.19@70.235,19.135 70.235,18.458 85.793,18.458 R68.2@86.11,18.775
  B.Cu w0.15: v1(55.498,32.601) 55.675,32.778 58.813,32.778 59.812,31.779 59.812,30.6 67.928,22.484 69.911,22.484 v1(71.756,20.639)
LORA_RESET_N: C68.1 R67.2 U1.57 U10.15 | length 49.5
  F.Cu w0.15: v2(60.085,41.925) 62.185,41.925 62.285,42.025 U1.57@62.985,42.025 ; R67.2@68.61,18.775 68.44,18.605 68.44,17.666 v1(68.938,17.168) ; C68.1@69.26,24.275 69.448,24.275 69.508,24.215 U10.15@70.235,24.215 70.962,24.215 v1(71.141,24.395) ; C68.1@69.285,24.325 69.385,24.325 69.485,24.425 69.585,24.425 69.685,24.525 69.885,24.525 69.985,24.625 70.085,24.625 70.185,24.725 70.785,24.725 70.985,24.925 70.985,27.125 71.685,27.825 71.685,27.925 71.785,28.025 71.685,28.125 71.685,28.325 71.385,28.625 v2(71.285,28.625)
  In3.Cu w0.15: v1(68.938,17.168) 69.818,18.047 69.818,23.071 v1(71.141,24.395)
  B.Cu w0.15: v2(60.085,41.925) 59.085,41.925 57.185,40.025 56.385,40.025 56.285,39.925 56.185,39.925 55.985,39.725 55.985,39.625 55.885,39.525 55.885,39.325 55.985,39.225 55.985,39.125 56.285,38.825 57.985,38.825 58.085,38.925 58.185,38.925 58.285,39.025 58.485,39.025 58.585,38.925 58.685,38.925 58.985,38.625 58.985,37.325 58.185,36.525 58.185,36.425 58.085,36.325 58.085,36.025 58.685,35.425 61.585,35.425 61.685,35.325 61.785,35.325 62.385,34.725 62.485,34.725 62.585,34.625 62.885,34.625 62.985,34.525 63.085,34.525 63.185,34.425 63.285,34.425 64.685,33.025 65.285,33.025 65.385,32.925 65.485,32.925 65.585,32.825 65.685,32.825 68.485,30.025 68.785,30.025 68.885,29.925 68.985,29.925 70.285,28.625 v2(71.285,28.625)
LORA_RF_ANT: C70.1 D5.1 J10.1 R73.2 | length 14.5
  F.Cu w0.151: 70.785,5.3 72.535,3.55 J10.1@76.66,3.55 ; R73.2@71.035,5.8 71.035,5.55 70.722,5.238 70.035,5.238 69.972,5.3 69.91,5.3 69.472,5.738 69.097,5.738 69.097,6.613 68.972,6.737 68.972,7.488 69.035,7.55 69.035,8.425 69.097,8.488 69.097,8.613 69.347,8.863 69.472,8.863 69.535,8.925 69.785,8.925 69.847,8.863 70.535,8.863 70.597,8.8 70.722,8.8 71.035,8.488 C70.1@71.035,8.3
LORA_RF_MODULE: C69.1 R73.1 U10.21 | length 9
  F.Cu w0.151: U10.21@70.222,12.3 70.785,12.3 71.722,11.363 71.722,11.238 71.785,11.175 71.785,8.863 72.285,8.363 72.285,8.238 71.847,8.238 71.348,7.738 70.847,7.738 70.347,7.238 70.347,7.05 R73.1@70.347,5.8
LORA_RXEN: R64.1 U1.55 U10.6 | length 45.1
  F.Cu w0.15: v1(62.373,41.029) 62.377,41.025 62.558,41.025 U1.55@63.435,41.025 ; v1(84.229,21.244) 84.408,21.423 84.408,21.675 U10.6@85.135,21.675 ; R64.1@86.11,20.025 86.11,19.498 86.96,19.498 v1(87.441,19.017)
  In3.Cu w0.15: v1(62.373,41.029) 66.155,37.247 66.155,30.672 69.861,26.966 69.861,24.061 v1(69.371,23.571) ; v1(84.229,21.244) 86.456,19.017 v1(87.441,19.017)
  B.Cu w0.15: v1(69.371,23.571) 81.903,23.571 v1(84.229,21.244)
LORA_SCK_U1: R70.1 U1.29 | length 30.4
  F.Cu w0.1: U1.29@51.185,37.725 v2(51.235,37.775) ; R70.1@66.885,47.875 67.185,48.175 67.235,48.175 67.285,48.225 67.735,48.225 67.785,48.175 67.835,48.175 68.435,47.575 v2(68.685,47.575)
  In5.Cu w0.1: v2(51.235,37.775) 53.135,37.775 53.235,37.875 55.135,37.875 55.185,37.925 58.485,37.925 58.535,37.975 58.635,37.975 59.085,38.425 59.285,38.425 59.335,38.475 59.385,38.475 59.435,38.525 59.485,38.525 60.785,39.825 60.985,39.825 61.035,39.875 61.135,39.875 61.185,39.925 61.235,39.925 61.585,40.275 62.435,40.275 62.485,40.325 62.585,40.325 62.635,40.375 62.685,40.375 63.385,41.075 66.685,41.075 66.735,41.125 66.785,41.125 67.785,42.125 68.585,42.125 68.635,42.175 68.685,42.175 68.735,42.225 68.785,42.225 69.135,42.575 70.585,42.575 70.685,42.675 70.735,42.675 70.935,42.875 71.085,42.875 71.135,42.925 71.185,42.925 71.285,43.025 71.285,43.075 71.335,43.125 71.335,43.275 71.535,43.475 71.535,43.525 71.635,43.625 71.635,43.975 71.535,44.075 71.535,44.125 68.685,46.975 v2(68.685,47.575)
LORA_SCK_U10: R70.2 U10.18 | length 32.5
  F.Cu w0.15: U10.18@70.235,20.405 73.379,23.549 73.379,25.986 ; v2(72.085,40.425) v2(72.085,42.825) ; 73.385,24.725 v2(73.385,34.825)
  In3.Cu w0.15: v2(67.585,47.725) 67.685,47.725 67.785,47.625 67.885,47.625 67.985,47.525 68.185,47.525 71.685,44.025 71.685,43.925 71.785,43.825 71.785,43.125 v2(72.085,42.825) ; v2(72.085,40.425) 72.085,39.225 72.185,39.125 72.185,37.525 72.285,37.425 72.285,37.325 72.385,37.225 72.385,37.025 72.485,36.925 72.485,36.825 72.585,36.725 72.585,36.625 72.685,36.525 72.685,36.425 72.785,36.325 72.785,36.225 72.885,36.125 72.885,35.925 72.985,35.825 72.985,35.725 73.085,35.625 73.085,35.525 73.185,35.425 73.185,35.325 73.285,35.225 73.285,35.125 73.385,35.025 v2(73.385,34.825)
LORA_TXEN: R63.1 U1.54 U10.7 | length 64
  F.Cu w0.15: v2(52.685,38.225) 53.085,38.225 53.785,38.925 53.885,38.925 54.585,39.625 54.585,40.125 54.685,40.225 54.685,40.325 54.885,40.525 55.185,40.525 v2(55.685,41.025) ; v2(60.285,41.125) 61.485,41.125 62.085,40.525 ; v1(60.911,40.576) 60.987,40.5 63.41,40.5 U1.54@63.435,40.525 ; v1(67.645,18.602) 67.645,18.689 68.454,19.498 69.26,19.498 R63.1@69.26,20.025 ; v1(72.129,19.457) 81.647,19.457 U10.7@85.135,22.945
  In3.Cu w0.15: v2(55.685,41.025) 57.885,41.025 57.985,41.125 58.085,41.125 58.185,41.225 60.185,41.225 v2(60.285,41.125) ; v2(56.785,28.025) 57.285,28.025 57.485,27.825 57.585,27.825 57.685,27.725 57.885,27.725 v2(58.085,27.525)
  B.Cu w0.15: v2(52.685,38.225) 53.485,37.425 53.485,35.425 53.385,35.325 53.385,34.825 52.785,34.225 52.785,34.125 52.685,34.025 52.685,33.925 52.585,33.825 52.585,33.425 52.685,33.325 52.685,33.225 52.785,33.125 52.785,33.025 56.785,29.025 v2(56.785,28.025) ; v2(58.085,27.525) 59.085,26.525 60.185,26.525 61.085,25.625 61.285,25.625 65.785,21.125 68.185,21.125 v2(69.185,20.125) ; v1(67.645,18.602) 68.5,19.457 v1(72.129,19.457)
LSE_IN: U1.8 X1.2 | length 19.9
  F.Cu w0.15: U1.8@48.385,47.525 v2(48.435,47.525) ; v2(65.935,44.525) X1.2@65.935,44.725
  In5.Cu w0.15: v2(48.435,47.525) 54.835,47.525 55.085,47.275 55.185,47.275 55.235,47.225 60.685,47.225 60.735,47.175 60.785,47.175 60.835,47.125 60.935,47.125 60.985,47.075 61.035,47.075 61.085,47.025 61.135,47.025 61.185,46.975 61.235,46.975 64.435,43.775 64.585,43.775 64.635,43.725 64.685,43.725 64.735,43.775 65.535,43.775 65.585,43.825 65.635,43.825 65.885,44.075 65.885,44.125 65.935,44.175 v2(65.935,44.525)
MIC_WAKE: R23.1 U1.67 U18.4 | length 31.9
  F.Cu w0.15: R23.1@57.51,27.275 57.51,27.901 57.313,28.098 57.313,28.525 U18.4@57.925,28.525 58.537,28.525 v1(58.717,28.525) ; v1(60.515,42.731) 62.558,44.774 62.558,47.025 U1.67@63.435,47.025
  In3.Cu w0.15: v1(58.717,28.525) 57.946,28.525 52.399,34.072 52.399,37.25 53.212,38.063 53.212,39.753 56.191,42.731 v1(60.515,42.731)
MIC_WAKE1: J_MIC1.5 R19.1 U17.1 U19.4 | length 48.3
  F.Cu w0.15: J_MIC1.5@10.275,30.275 11.052,30.275 11.86,31.083 ; U19.4@12.017,36.025 11.458,36.025 11.458,34.954 11.86,34.552 R19.1@11.86,32.525 11.86,31.998 11.86,31.083 ; U17.1@47.785,30.975 46.647,30.975 44.241,33.381 35.942,33.381 35.691,33.131 27.785,33.131 27.607,33.31 27.607,33.491 25.485,35.612 20.13,35.612 16.392,31.874 16.392,31.171 15.996,30.775 12.168,30.775 11.86,31.083
MIC_WAKE2: J_MIC2.5 R20.1 U17.2 U20.4 | length 42.7
  F.Cu w0.112: v1@40.959,12.44 40.959,12.508 40.977,12.525 U20.4@41.517,12.525
  F.Cu w0.15: v1(40.779,12.44) v1@40.959,12.44 ; v1(41.61,10.284) R20.1@41.61,9.525 41.61,8.998 41.682,8.998 43.287,7.392 45.935,7.392 J_MIC2.5@45.935,6.615 ; v1(46.554,30.325) U17.2@47.785,30.325
  In3.Cu w0.15: v1(40.779,12.44) 41.61,11.608 v1(41.61,10.284) 40.196,8.87 40.196,7.076 40.518,6.753 41.844,6.753 45.672,10.581 45.672,29.443 v1(46.554,30.325)
MIC_WAKE3: J_MIC3.5 R21.1 U17.4 U21.4 | length 77.7
  F.Cu w0.112: 94.431,8.399 94.708,8.399
  F.Cu w0.15: U17.4@47.785,29.025 v1(49.024,29.025) ; v1(86.603,10.497) 91.635,10.497 92.358,9.775 R21.1@92.86,9.775 92.86,8.965 93.426,8.399 94.431,8.399 ; U21.4@95.267,9.275 94.708,9.275 94.708,8.399 94.818,8.399 95.514,7.704 95.514,6.291 95.967,5.838 97.935,5.838 J_MIC3.5@97.935,6.615
  In3.Cu w0.15: v1(49.024,29.025) 49.573,28.477 49.573,17.384 52.815,14.142 52.815,11.554 61.574,2.795 78.901,2.795 v1(86.603,10.497)
MIC_WAKE4: J_MIC4.5 R22.1 U17.5 U22.4 | length 75.8
  F.Cu w0.15: U17.5@47.785,28.375 48.812,28.375 48.901,28.285 v1(50.534,28.285) ; v1(101.779,22.036) 101.779,21.778 103.032,20.525 U22.4@104.017,20.525 ; R22.1@103.36,23.275 103.36,23.802 103.549,23.802 v1(103.737,23.991) 105.602,23.991 106.318,23.275 J_MIC4.5@107.095,23.275
  In3.Cu w0.15: v1(50.534,28.285) 52.38,26.439 55.101,26.439 62.891,18.649 62.891,16.512 66.412,12.991 92.736,12.991 v1(101.779,22.036) ; v1(101.779,22.036) v1(101.779,22.036) ; v1(103.737,23.991) v1(101.779,22.036) v1(101.779,22.036)
MIC_WAKE12_OR_1V8: U17.3 U17.9 | length 6.7
  F.Cu w0.15: U17.3@47.785,29.675 50.631,29.675 v1(51.563,28.743) ; v1(52.362,28.053) 52.558,27.858 52.558,27.725 U17.9@53.585,27.725
  B.Cu w0.15: v1(51.563,28.743) 52.253,28.053 v1(52.362,28.053)
MIC_WAKE34_OR_1V8: U17.6 U17.10 | length 6.2
  F.Cu w0.15: U17.6@47.785,27.725 51.29,27.725 52.146,28.581 52.582,28.581 52.789,28.375 U17.10@53.585,28.375
MIC_WAKE_OR_1V8: U17.8 U18.3 | length 3.5
  F.Cu w0.112: U17.8@53.585,27.075 54.699,27.075 55.635,28.011
  F.Cu w0.15: 55.635,28.011 55.931,28.011 U18.3@56.445,28.525
NOR_CLK_U1: R8.1 U1.38 | length 24.2
  F.Cu w0.15: U1.38@55.685,37.275 56.135,41.175 56.585,41.625 57.985,49.325 v1(59.185,50.525) ; R8.1@57.91,59.05 56.66,57.8 56.66,57.05 57.335,56.775 57.485,56.675 v1(58.485,55.275)
  In3.Cu w0.15: v1@58.385,55.225 58.485,55.125 58.485,54.925 58.585,54.825 58.585,54.725 58.685,54.625 58.685,54.525 58.785,54.425 58.785,54.325 58.885,54.225 58.885,54.125 58.985,54.025 58.985,53.825 59.085,53.725 59.085,53.625 59.185,53.525 v1@59.185,50.625
NOR_CLK_U2: R8.2 U2.16 | length 30.5
  F.Cu w0.15: R8.2@58.51,59.025 v1(61.885,55.875) ; v1(82.785,47.925) 84.285,47.925 84.29,47.925 U2.16@84.335,47.97
  B.Cu w0.15: v1(61.885,55.875) 67.035,55.325 73.285,53.025 73.635,52.675 74.185,51.525 74.535,51.075 81.757,48.317 81.529,47.72 82.09,47.506 82.318,48.103 v1(82.785,47.925)
NOR_IO0_U1: R9.1 U1.40 | length 30.8
  F.Cu w0.15: U1.40@56.685,37.275 56.735,38.025 57.268,39.953 56.603,40.137 56.763,40.715 57.428,40.531 57.588,41.109 56.922,41.293 57.082,41.872 57.747,41.688 57.907,42.266 57.242,42.45 57.402,43.028 58.067,42.844 58.227,43.423 57.562,43.606 57.722,44.185 58.387,44.001 58.547,44.579 57.882,44.763 58.041,45.341 58.707,45.158 58.866,45.736 58.201,45.92 58.361,46.498 59.026,46.314 v1(60.135,50.325) ; v1(64.185,54.075) R9.1@64.185,54.95
  B.Cu w0.15: v1(60.135,50.325) 61.735,49.875 61.985,49.925 62.235,50.175 62.509,50.593 63.136,50.182 63.465,50.684 62.838,51.095 63.185,51.625 v1(64.185,54.075)
NOR_IO0_U2: R9.2 U2.15 | length 23.8
  F.Cu w0.15: R9.2@64.185,55.6 v1(65.035,56.075) ; v1(78.785,50.925) 82.41,47.3 83.66,47.3 84.285,46.675 84.31,46.7 U2.15@84.335,46.7
  B.Cu w0.15: v1(65.035,56.075) 74.635,54.225 76.185,52.675 76.835,51.325 77.185,51.025 77.635,50.875 v1(78.785,50.925)
NOR_IO1_U1: R10.1 U1.41 | length 21.7
  F.Cu w0.15: U1.41@57.185,37.275 57.235,38.025 59.835,47.725 v1(61.485,49.375) ; v1(65.535,53.975) R10.1@65.685,54.95
  B.Cu w0.15: v1(61.485,49.375) 64.835,50.075 65.035,50.325 65.785,51.825 v1(65.535,53.975)
NOR_IO1_U2: R10.2 U2.8 | length 32.9
  F.Cu w0.15: R10.2@65.685,55.6 66.135,56.075 67.535,56.125 v1(70.035,53.625) ; U2.8@75.035,39.08 v1(75.035,39.225)
  B.Cu w0.15: v1(70.035,53.625) 71.685,51.425 74.035,49.075 74.681,42.707 76.539,42.896 76.599,42.299 74.742,42.11 74.803,41.513 76.66,41.702 76.72,41.105 74.863,40.916 74.924,40.319 76.781,40.508 76.842,39.911 74.984,39.722 v1(75.035,39.225)
NOR_IO2_U1: R11.1 U1.42 | length 23.6
  F.Cu w0.15: U1.42@57.685,37.275 57.885,38.925 58.885,39.975 v1(62.085,48.525) ; v1(67.185,54.075) R11.1@67.185,54.95
  B.Cu w0.15: v1(62.085,48.525) 66.785,49.275 67.035,49.575 68.285,51.675 68.335,52.875 v1(67.185,54.075)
